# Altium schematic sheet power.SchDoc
size A4; SheetNumber: 4; SheetTotal: 5
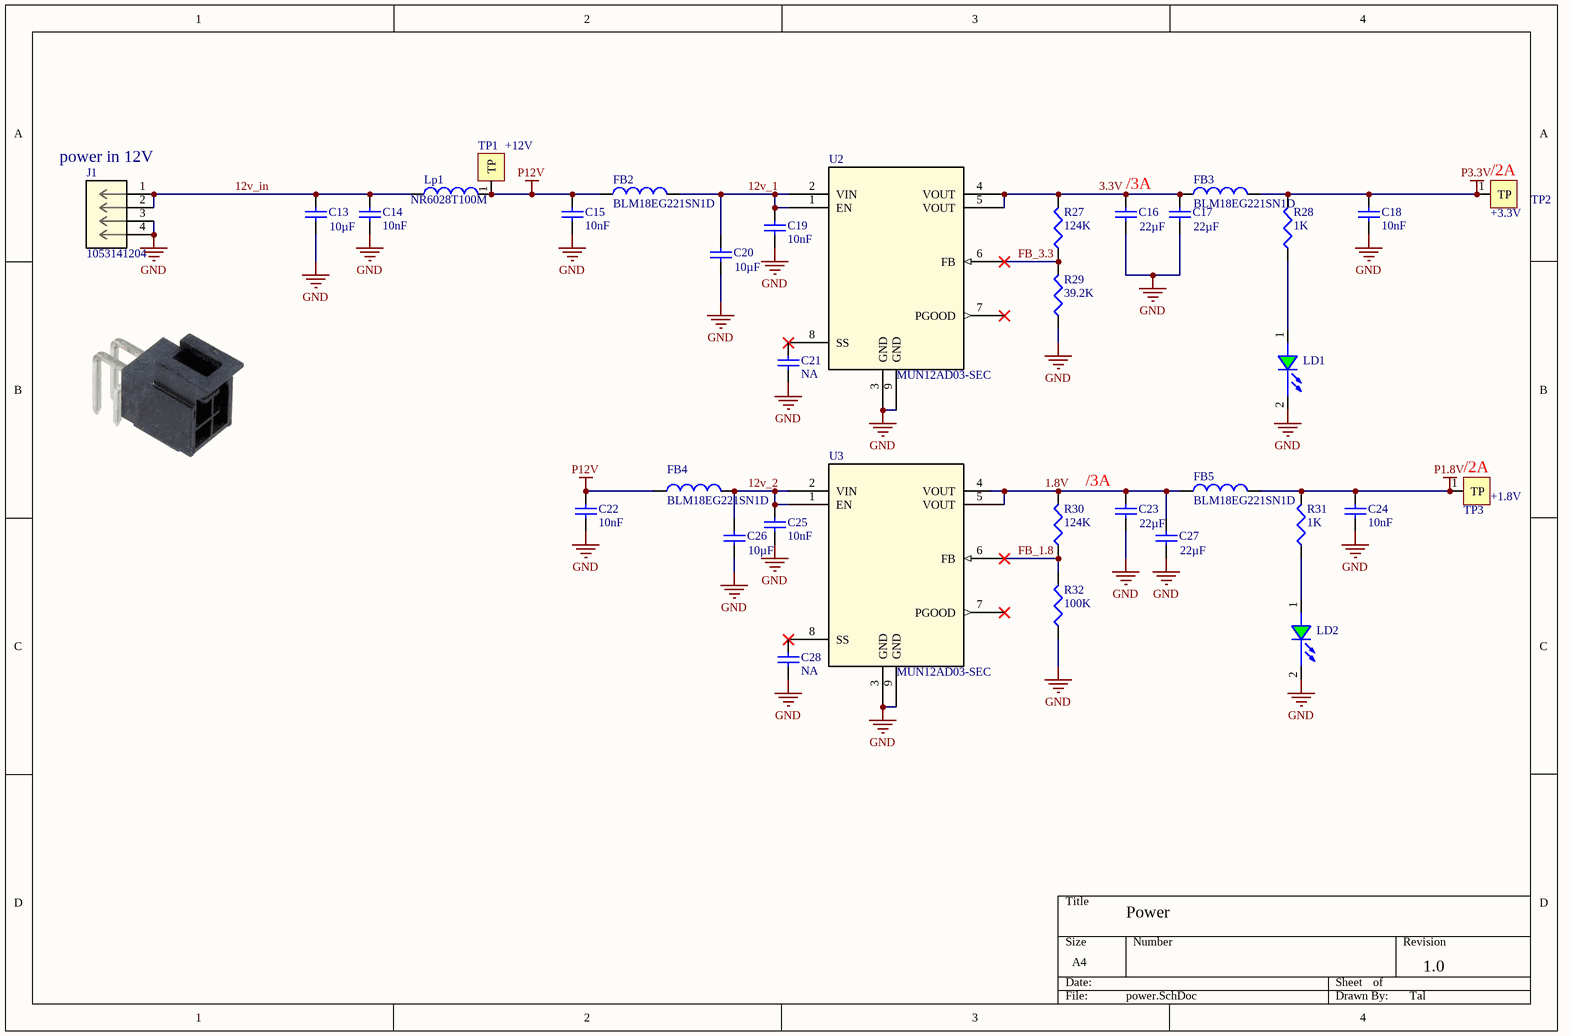
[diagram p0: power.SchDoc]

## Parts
C13  Capacitance: 10µF  [C0603]  (hidden comment: 10uF 25V)
C14  Capacitance: 10nF  [C0402]  (hidden comment: 10nF 25V)
C15  Capacitance: 10nF  [C0402]  (hidden comment: 10nF 25V)
C16  Capacitance: 22µF  [C0603]  (hidden comment: 22uF 16V)
C17  Capacitance: 22µF  [C0603]  (hidden comment: 22uF 16V)
C18  Capacitance: 10nF  [C0402]  (hidden comment: 10nF 25V)
C19  Capacitance: 10nF  [C0402]  (hidden comment: 10nF 25V)
C20  Capacitance: 10µF  [C0603]  (hidden comment: 10uF 25V)
C21  NA  [C0402]
C22  Capacitance: 10nF  [C0402]  (hidden comment: 10nF 25V)
C23  Capacitance: 22µF  [C0603]  (hidden comment: 22uF 16V)
C24  Capacitance: 10nF  [C0402]  (hidden comment: 10nF 25V)
C25  Capacitance: 10nF  [C0402]  (hidden comment: 10nF 25V)
C26  Capacitance: 10µF  [C0603]  (hidden comment: 10uF 25V)
C27  Capacitance: 22µF  [C0603]  (hidden comment: 22uF 16V)
C28  NA  [C0402]
FB2  BLM18EG221SN1D  [fb0603]
FB3  BLM18EG221SN1D  [FB0603]
FB4  BLM18EG221SN1D  [fb0603]
FB5  BLM18EG221SN1D  [fb0603]
J1  1053141204  [CON_1053141204]
LD1  APT1608SGC  [LED_0603_Green]  (value not drawn)
LD2  APT1608SGC  [LED_0603_Green]  (value not drawn)
Lp1  NR6028T100M  [ind6x6_H3]
R27  124K  [R0402]
R28  1K  [R0402]
R29  39.2K  [R0402]
R30  124K  [R0402]
R31  1K  [R0402]
R32  100K  [R0402]
TP1  +12V  [TP_2x1.8]
TP2  +3.3V  [TP_2x1.8]
TP3  +1.8V  [TP_2x1.8]
U2  MUN12AD03-SEC  [SO8_MUN12AD_DEA]
U3  MUN12AD03-SEC  [SO8_MUN12AD_DEA]

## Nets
GND: C13.1 C14.1 C15.1 C16.1 C17.1 C18.1 C19.1 C20.1 C21.1 C22.1 C23.1 C24.1 C25.1 C26.1 C27.1 C28.1 J1.3 J1.4 LD1.2(CATHODE) LD2.2(CATHODE) R29.1 R32.1 U2.3(GND) U2.9(GND) U3.3(GND) U3.9(GND)
P1.8V: C24.2 FB5.2 R31.2 TP3.1(TP)
P3.3V: C18.2 FB3.2 R28.2 TP2.1(TP)
P12V: C15.2 C22.2 FB2.1 FB4.1 Lp1.2 TP1.1(TP)
1.8V: C23.2 C27.2 FB5.1 R30.2 U3.4(VOUT) U3.5(VOUT)
3.3V: C16.2 C17.2 FB3.1 R27.2 U2.4(VOUT) U2.5(VOUT)
12v_1: C19.2 C20.2 FB2.2 U2.1(EN) U2.2(VIN)
12v_2: C25.2 C26.2 FB4.2 U3.1(EN) U3.2(VIN)
12v_in: C13.2 C14.2 J1.1 J1.2 Lp1.1
FB_1.8: R30.1 R32.2 U3.6(FB)
FB_3.3: R27.1 R29.2 U2.6(FB)
NetC21_2: C21.2 U2.8(SS)
NetC28_2: C28.2 U3.8(SS)
NetLD1_1: LD1.1(ANODE) R28.1
NetLD2_1: LD2.1(ANODE) R31.1

Not connected (* = marked no-connect by the designer): U2 7(PGOOD)*; U3 7(PGOOD)*

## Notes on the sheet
- (near J1) power in 12V
- (near TP2) /2A
- (near C16) /3A
- /3A
- (near TP3) /2A
- Power
- 1.0
- Tal

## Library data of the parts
C13 C20 C26 = CAP CER 10uF 10V 10% X5R 0603: CAP CER 10UF 25V 10% X5R 0603; Manufacturer Part Number: C1608X5R1A106K; Manufacturer: TDK Corporation; LANDA P/N: ECP-000008; Voltage - Rated: 10V
C14 C15 C18 C19 C22 C24 C25 = CAP CER 12nF 25V 10% X7R 0402: CAP CER 10nF 25V 10% X5R 0402; Manufacturer Part Number: GRM155R71E123KA61D; Manufacturer: Murata Electronics North America; LANDA P/N: ECP-000042
C16 C17 C23 C27 = CAP CER 10uF 10V 10% X5R 0603: CAP CER 22UF 16V 10% X5R 0603; Manufacturer Part Number: C1608X5R1A106K; Manufacturer: TDK Corporation; LANDA P/N: ECP-000008; Voltage - Rated: 10V
C21 C28 = CAP CER 6.8pF 50V NP0 0402: CAP CER NA 50V NP0 0402; Manufacturer Part Number: C1005C0G1H6R8D; Manufacturer: TDK Corporation; LANDA P/N: ECP-000033
FB2-FB5 = BK1608HS600-T: FERRITE BEAD 220_OHM@100MHz 0603 2A 50mohm_DC; Manufacturer: Taiyo Yuden; LANDA P/N: EIN-000010
J1 = 1053141204: No Description Available; Mfr_Name: Molex Connector Corporation
LD1 LD2 = APT1608SGC: LED 1.6X0.8MM 568NM GRN CLR SMD; Manufacturer: Kingbright Corp; LANDA P/N: EDI-000006
Lp1 = NR6028T100M: INDUCTOR 10UH 1.9A 20% SMD; Manufacturer: Taiyo Yuden; Shielding: Shielded; LANDA P/N: EIN-000003
R27 R30 = RES 15.4K OHM 1/10W 1% 0402 SMD: RES 124K OHM 1/10W 1% 0402 SMD; Manufacturer: Panasonic Electronic Components; Manufacturer Part Number: ERJ-2RKF1542X; Power (Watts): 0.1W, 1/10W; LANDA P/N: ERS-000060
R28 R31 = RES 3.09K OHM 1/16W 1% 0402: RES 1K OHM 1/16W 1% 0402; Manufacturer Part Number: RMCF0402FT3K09; Manufacturer: Stackpole Electronics Inc; Power (Watts): 0.063W, 1/16W; LANDA P/N: ERS-000063
R29 = RES 15.4K OHM 1/10W 1% 0402 SMD: RES 39.2K OHM 1/10W 1% 0402 SMD; Manufacturer: Panasonic Electronic Components; Manufacturer Part Number: ERJ-2RKF1542X; Power (Watts): 0.1W, 1/10W; LANDA P/N: ERS-000060
R32 = RES 3.09K OHM 1/16W 1% 0402: RES 100K OHM 1/16W 1% 0402; Manufacturer Part Number: RMCF0402FT3K09; Manufacturer: Stackpole Electronics Inc; Power (Watts): 0.063W, 1/16W; LANDA P/N: ERS-000063
TP1-TP3 = TP mini_2: TP PC MINIATURE SMT; Manufacturer: Keystone Electronics; Manufacturer Part Number: 5015; Assembly: N.A; LANDA P/N: ECN-000032
U2 U3 = MUN12AD03-SEC: No Description Available; Mfr_Name: Delta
